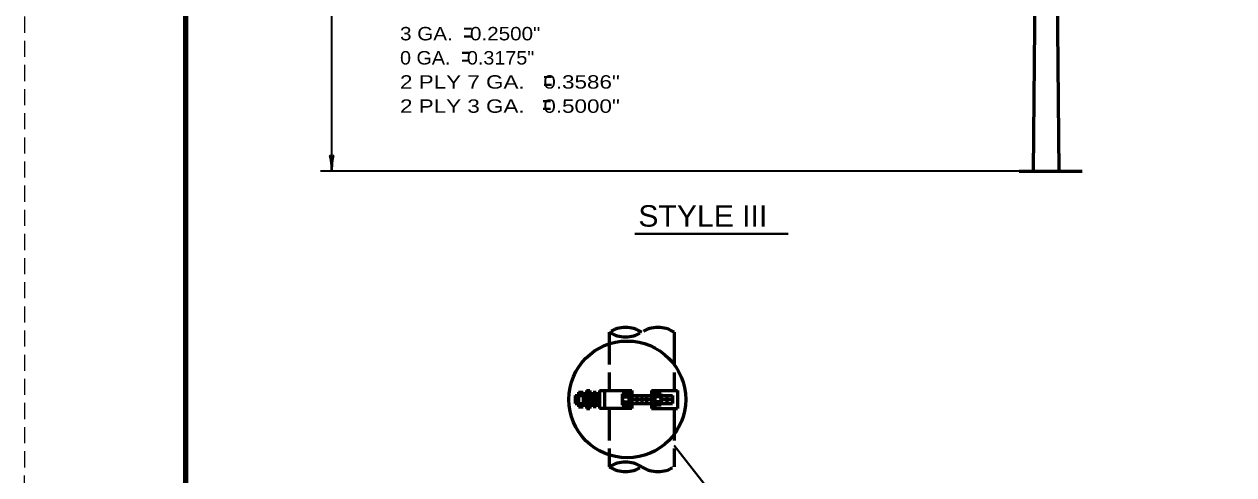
# Model space of a CAD drawing. Extents: x -1 to 679, y -228 to 440.
# Drawn here: x -1 to 224.4, y 192.8 to 276.8 of the extents above; entities that cross this region are included whole.
import ezdxf

# ---------------------------------------------------------------- set-up
doc = ezdxf.new("R2010")
doc.units = 0
doc.linetypes.add('LONG_DASHED', pattern=[7.5, 6, -1.5])
doc.linetypes.add('MEDIUM_DASHED', pattern=[4.5, 3, -1.5])
doc.layers.add('1', color=7, linetype='Continuous', lineweight=35)
doc.layers.add('61', color=7, linetype='Continuous', lineweight=35)

msp = doc.modelspace()

# ---------------------------------------------------------------- linework, layer by layer
at = {"layer": '1', "linetype": 'MEDIUM_DASHED', "lineweight": 13}
msp.add_line((-0.979, 440.237), (-1.039, 0.197), dxfattribs=at)
at = {"layer": '1'}
for p, q in [((56.274, 249.522), (56.274, 372.411)), ((184.393, 249.411), (54.189, 249.411))]:
    msp.add_line(p, q, dxfattribs=at)
at = {"layer": '1', "lineweight": 53}
for p, q in [((190.893, 344.411), (191.784, 249.412)), ((184.393, 249.411), (196.143, 249.411)), ((101.647, 207.65), (101.647, 206.13)), ((101.647, 207.65), (106.187, 207.65)), ((102.247, 208.25), (102.247, 205.53)), ((102.247, 208.25), (103.167, 208.25)), ((103.167, 208.25), (103.167, 205.53)), ((103.767, 208.55), (103.767, 205.231)), ((103.767, 208.55), (104.367, 208.55)), ((104.367, 208.55), (104.367, 205.231)), ((104.987, 208.25), (104.987, 205.53)), ((104.987, 208.25), (105.587, 208.25)), ((105.587, 208.25), (105.587, 205.53)), ((106.187, 208.55), (106.187, 205.231)), ((106.187, 208.55), (112.227, 208.55)), ((107.087, 208.55), (107.087, 205.231)), ((110.427, 207.951), (111.627, 207.951)), ((110.427, 207.951), (110.427, 205.831)), ((111.627, 208.55), (111.627, 205.231)), ((112.227, 208.55), (112.227, 205.231)), ((113.147, 207.65), (113.147, 206.13)), ((114.047, 207.65), (114.047, 206.13)), ((114.967, 207.65), (114.967, 206.13)), ((115.867, 208.55), (115.867, 205.231)), ((115.867, 208.55), (120.707, 208.55)), ((116.467, 208.55), (116.467, 205.231)), ((117.687, 207.951), (116.487, 207.951)), ((117.687, 207.951), (117.687, 205.831)), ((118.747, 207.65), (118.747, 206.13)), ((119.787, 207.65), (119.787, 206.13)), ((120.707, 208.55), (120.707, 205.231)), ((101.647, 206.13), (106.187, 206.13)), ((101.947, 207.03), (101.947, 206.731)), ((102.247, 205.53), (103.167, 205.53)), ((103.767, 205.231), (104.367, 205.231)), ((105.587, 205.53), (104.987, 205.53)), ((112.227, 205.231), (106.187, 205.231)), ((110.427, 205.831), (111.627, 205.831)), ((110.727, 207.35), (111.627, 207.35)), ((110.727, 206.43), (111.627, 206.43)), ((112.687, 207.19), (112.687, 206.59)), ((113.587, 207.19), (113.587, 206.59)), ((114.507, 207.19), (114.507, 206.59)), ((115.407, 207.19), (115.407, 206.59)), ((115.867, 205.231), (120.707, 205.231)), ((117.387, 207.35), (116.487, 207.35)), ((117.387, 206.43), (116.487, 206.43)), ((117.687, 205.831), (116.487, 205.831)), ((117.687, 206.731), (117.387, 206.43)), ((117.387, 206.43), (117.687, 206.13)), ((118.207, 207.19), (118.207, 206.59)), ((119.267, 207.19), (119.267, 206.59))]:
    msp.add_line(p, q, dxfattribs=at)
at = {"layer": '1', "lineweight": 40}
for p, q in [((112.77, 237.748), (141.364, 237.748)), ((120.107, 198.311), (130.625, 184.906))]:
    msp.add_line(p, q, dxfattribs=at)
at = {"layer": '1', "linetype": 'LONG_DASHED', "lineweight": 53}
for p, q in [((108.007, 219.43), (108.007, 208.55)), ((120.107, 219.43), (120.107, 208.55)), ((108.007, 205.231), (108.007, 194.331)), ((120.107, 205.231), (120.107, 194.331))]:
    msp.add_line(p, q, dxfattribs=at)
at = {"layer": '1', "lineweight": 53}
for points in [[(187.893, 344.411), (187.86, 340.911), (187.823, 336.911), (187.002, 249.412)], [(110.427, 207.65), (110.727, 207.35), (110.427, 207.03)], [(112.227, 207.65), (113.147, 207.65), (114.047, 207.65), (114.967, 207.65), (115.867, 207.65)], [(117.687, 207.65), (117.387, 207.35), (117.687, 207.03)], [(117.687, 207.65), (118.747, 207.65), (119.787, 207.65)], [(110.427, 206.731), (110.727, 206.43), (110.427, 206.13)], [(112.227, 206.13), (114.047, 206.13), (115.867, 206.13)], [(117.687, 206.13), (118.747, 206.13), (119.787, 206.13)]]:
    msp.add_lwpolyline(points, dxfattribs=at)
msp.add_circle((111.362, 206.894), 10.886, dxfattribs=at)
at = {"layer": '1', "linetype": 'LONG_DASHED', "lineweight": 53}
for centre, start, end in [((111.027, 214.705), 57.42639, 122.57361), ((111.027, 224.172), 237.42639, 302.57361), ((117.075, 214.705), 57.42639, 122.57361), ((111.027, 189.606), 57.42639, 122.57361), ((111.027, 199.073), 237.42639, 302.57361), ((117.075, 199.073), 237.42639, 302.57361)]:
    msp.add_arc(centre, 5.617, start, end, dxfattribs=at)
at = {"layer": '1', "lineweight": 40}
for centre, major_axis, ratio, start_param, end_param in [((55.998, 250.613), (0.156, -1.786), 0.122415, 0.8963533, 3.1415927), ((56.486, 250.642), (-0.176, -1.756), 0.07063, 3.1407148, 5.41811)]:
    msp.add_ellipse(centre, major_axis=major_axis, ratio=ratio, start_param=start_param, end_param=end_param, dxfattribs=at)
at = {"layer": '61', "lineweight": 158}
msp.add_lwpolyline([(668.061, 430.237), (29.021, 430.237), (29.021, 10.217)], dxfattribs=at)

# ---------------------------------------------------------------- texts
at = {"layer": '1'}
for s, height, width, p in [('3 GA.   0.2500"', 2.5, 1.15, (69.01, 273.813)), ('=', 4, 0.55, (80.784, 273.351)), ('0 GA.   0.3175"', 2.5, 1.1, (69.01, 269.313)), ('=', 4, 0.55, (80.438, 268.848)), ('2 PLY 7 GA.   0.3586"', 2.5, 1.25, (69.01, 264.813)), ('=', 4, 0.55, (95.675, 264.344)), ('2 PLY 3 GA.   0.5000"', 2.5, 1.25, (69.01, 260.313)), ('=', 4, 0.55, (95.502, 259.841)), ('STYLE III', 4, 1.05, (113.424, 239.093))]:
    msp.add_text(s, height=height, dxfattribs=dict(at, width=width)).set_placement(p)

doc.saveas('drawing.dxf')
